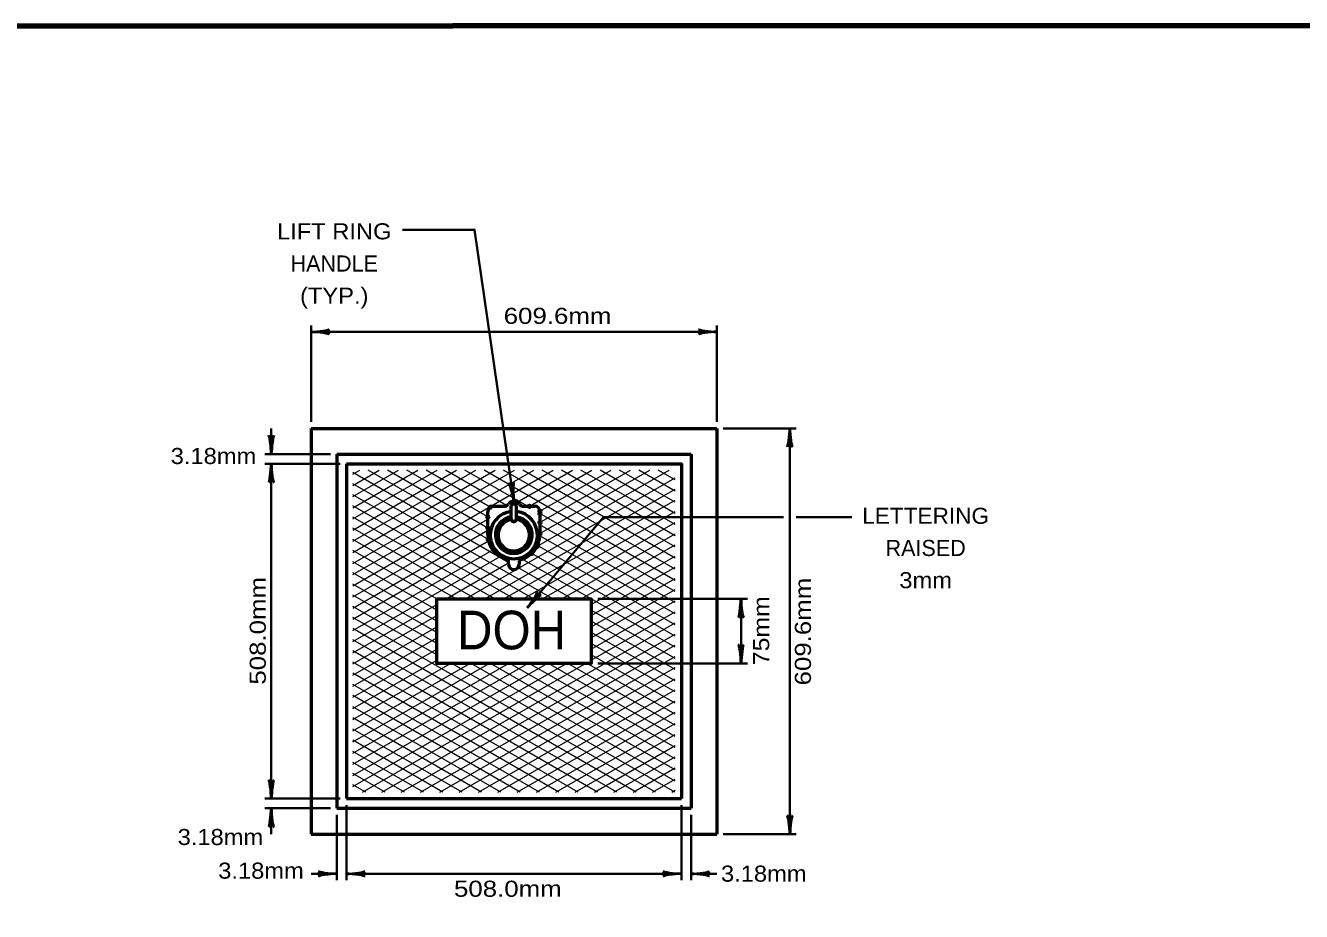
# Model space of a CAD drawing. Extents: x 918 to 1774, y -8 to 536.
# Drawn here: x 1291.6 to 1529.3, y 364.7 to 529.8 of the extents above; entities that cross this region are included whole.
import ezdxf
from ezdxf.enums import TextEntityAlignment as Align

# ---------------------------------------------------------------- set-up
doc = ezdxf.new("R2010")
doc.units = 0
doc.header["$LTSCALE"] = 1.2
doc.header["$PDMODE"] = 32
doc.header["$PDSIZE"] = 0.6
doc.layers.add('1', color=7, linetype='Continuous', lineweight=35)

msp = doc.modelspace()

# ---------------------------------------------------------------- linework, layer by layer
at = {"layer": '1'}
for p, q in [((1344.782, 455.942), (1344.782, 473.928)), ((1420.382, 455.942), (1420.382, 473.928)), ((1344.782, 472.728), (1420.382, 472.728)), ((1337.367, 454.743), (1337.367, 449.942)), ((1421.582, 454.743), (1435.184, 454.743)), ((1433.984, 454.743), (1433.984, 379.143)), ((1348.382, 449.942), (1336.167, 449.942)), ((1350.182, 448.143), (1336.167, 448.143)), ((1337.367, 448.143), (1337.367, 385.743)), ((1385.08, 421.334), (1399.25, 438.183)), ((1399.25, 438.183), (1432.784, 438.183)), ((1435.184, 438.183), (1445.504, 438.183)), ((1398.182, 422.942), (1426.081, 422.942)), ((1424.881, 422.942), (1424.881, 410.942)), ((1398.182, 410.942), (1426.081, 410.942)), ((1350.182, 385.743), (1336.167, 385.743)), ((1348.382, 383.942), (1336.167, 383.942)), ((1337.367, 383.942), (1337.367, 379.143)), ((1349.582, 382.743), (1349.582, 370.528)), ((1351.382, 384.543), (1351.382, 370.528)), ((1413.782, 384.543), (1413.782, 370.528)), ((1415.582, 382.743), (1415.582, 370.528)), ((1421.582, 379.143), (1435.184, 379.143)), ((1344.782, 371.728), (1349.582, 371.728)), ((1351.382, 371.728), (1413.782, 371.728)), ((1415.582, 371.728), (1420.382, 371.728))]:
    msp.add_line(p, q, dxfattribs=at)
at = {"layer": '1', "lineweight": 53}
for p, q in [((1344.782, 454.743), (1344.782, 379.143)), ((1344.782, 454.743), (1420.382, 454.743)), ((1420.382, 454.743), (1420.382, 379.143)), ((1349.582, 449.942), (1349.582, 383.942)), ((1349.582, 449.942), (1415.582, 449.942)), ((1415.582, 449.942), (1415.582, 383.942)), ((1351.382, 448.143), (1351.382, 385.743)), ((1378.683, 440.226), (1378.681, 440.218)), ((1378.681, 440.218), (1380.742, 440.218)), ((1378.681, 440.218), (1380.742, 440.218)), ((1382.083, 437.826), (1382.083, 440.218)), ((1383.055, 437.826), (1383.055, 440.218)), ((1384.396, 440.218), (1386.457, 440.218)), ((1384.396, 440.218), (1386.457, 440.218)), ((1377.709, 434.969), (1377.709, 439.245)), ((1377.709, 434.969), (1377.709, 439.245)), ((1387.429, 439.245), (1387.429, 435.008)), ((1387.429, 439.245), (1387.429, 435.008)), ((1381.578, 429.37), (1381.578, 430.012)), ((1381.578, 429.37), (1381.578, 430.012)), ((1383.541, 430.012), (1383.541, 429.37)), ((1383.541, 430.012), (1383.541, 429.37)), ((1351.382, 385.743), (1413.782, 385.743)), ((1349.582, 383.942), (1415.582, 383.942)), ((1344.782, 379.143), (1420.382, 379.143))]:
    msp.add_line(p, q, dxfattribs=at)
at = {"layer": '1', "lineweight": 13}
for p, q in [((1352.582, 446.186), (1353.893, 446.942)), ((1352.582, 444.107), (1357.493, 446.942)), ((1352.582, 442.029), (1361.093, 446.942)), ((1352.582, 439.95), (1364.693, 446.942)), ((1352.582, 437.872), (1368.293, 446.942)), ((1352.582, 435.793), (1371.893, 446.942)), ((1352.582, 433.715), (1375.493, 446.942)), ((1352.582, 431.637), (1379.093, 446.942)), ((1352.582, 429.558), (1382.693, 446.942)), ((1352.582, 427.48), (1386.293, 446.942)), ((1352.582, 425.401), (1389.893, 446.942)), ((1377.813, 434.022), (1355.435, 446.942)), ((1377.709, 436.161), (1359.035, 446.942)), ((1377.709, 438.24), (1362.635, 446.942)), ((1378.163, 440.056), (1366.235, 446.942)), ((1381.219, 440.37), (1369.835, 446.942)), ((1385.083, 440.218), (1373.435, 446.942)), ((1412.582, 426.419), (1377.035, 446.942)), ((1412.582, 428.498), (1380.635, 446.942)), ((1383.179, 440.988), (1393.493, 446.942)), ((1412.582, 430.576), (1384.235, 446.942)), ((1385.445, 440.218), (1397.093, 446.942)), ((1386.871, 432.727), (1411.493, 446.942)), ((1387.426, 439.283), (1400.693, 446.942)), ((1387.429, 437.206), (1404.293, 446.942)), ((1387.429, 435.128), (1407.893, 446.942)), ((1412.582, 432.655), (1387.835, 446.942)), ((1412.582, 434.733), (1391.435, 446.942)), ((1412.582, 436.812), (1395.035, 446.942)), ((1412.582, 438.89), (1398.635, 446.942)), ((1412.582, 440.969), (1402.235, 446.942)), ((1412.582, 443.047), (1405.835, 446.942)), ((1412.582, 445.126), (1409.435, 446.942)), ((1381.578, 429.771), (1352.582, 446.511)), ((1373.524, 422.942), (1412.582, 445.493)), ((1389.804, 422.942), (1352.582, 444.433)), ((1386.204, 422.942), (1352.582, 442.354)), ((1377.124, 422.942), (1412.582, 443.414)), ((1382.604, 422.942), (1352.582, 440.276)), ((1380.724, 422.942), (1412.582, 441.336)), ((1379.004, 422.942), (1352.582, 438.197)), ((1352.582, 423.323), (1377.709, 437.83)), ((1384.324, 422.942), (1412.582, 439.257)), ((1412.582, 424.341), (1387.429, 438.863)), ((1375.404, 422.942), (1352.582, 436.119)), ((1352.582, 421.244), (1377.709, 435.751)), ((1412.582, 422.262), (1387.429, 436.785)), ((1387.924, 422.942), (1412.582, 437.179)), ((1391.524, 422.942), (1412.582, 435.101)), ((1371.804, 422.942), (1352.582, 434.04)), ((1352.582, 419.166), (1377.868, 433.764)), ((1412.582, 418.106), (1386.95, 432.904)), ((1412.582, 420.184), (1387.405, 434.72)), ((1395.124, 422.942), (1412.582, 433.022)), ((1352.582, 417.087), (1378.627, 432.124)), ((1368.204, 422.942), (1352.582, 431.962)), ((1352.582, 415.009), (1380.008, 430.843)), ((1412.582, 413.949), (1384.133, 430.374)), ((1412.582, 416.027), (1385.893, 431.436)), ((1396.982, 421.937), (1412.582, 430.944)), ((1368.182, 420.877), (1352.582, 429.883)), ((1369.924, 422.942), (1381.578, 429.671)), ((1393.404, 422.942), (1383.29, 428.782)), ((1396.982, 419.858), (1412.582, 428.865)), ((1368.182, 418.798), (1352.582, 427.805)), ((1368.182, 416.72), (1352.582, 425.727)), ((1396.982, 417.78), (1412.582, 426.787)), ((1368.182, 414.641), (1352.582, 423.648)), ((1396.982, 415.702), (1412.582, 424.708)), ((1352.582, 412.93), (1368.182, 421.937)), ((1368.182, 412.563), (1352.582, 421.57)), ((1396.982, 413.623), (1412.582, 422.63)), ((1412.582, 411.87), (1396.982, 420.877)), ((1352.582, 410.852), (1368.182, 419.858)), ((1408.958, 386.942), (1352.582, 419.491)), ((1357.97, 386.942), (1412.582, 418.473)), ((1396.982, 411.545), (1412.582, 420.551)), ((1412.582, 409.792), (1396.982, 418.798)), ((1352.582, 408.773), (1368.182, 417.78)), ((1405.358, 386.942), (1352.582, 417.413)), ((1361.57, 386.942), (1412.582, 416.394)), ((1412.582, 407.713), (1396.982, 416.72)), ((1352.582, 406.695), (1368.182, 415.702)), ((1401.758, 386.942), (1352.582, 415.334)), ((1352.582, 404.617), (1368.182, 413.623)), ((1365.17, 386.942), (1412.582, 414.316)), ((1412.582, 405.635), (1396.982, 414.641)), ((1398.158, 386.942), (1352.582, 413.256)), ((1352.582, 402.538), (1368.182, 411.545)), ((1368.77, 386.942), (1412.582, 412.238)), ((1412.582, 403.556), (1396.982, 412.563)), ((1394.558, 386.942), (1352.582, 411.177)), ((1352.582, 400.46), (1370.739, 410.942)), ((1352.582, 398.381), (1374.339, 410.942)), ((1352.582, 396.303), (1377.939, 410.942)), ((1352.582, 394.224), (1381.539, 410.942)), ((1352.582, 392.146), (1385.139, 410.942)), ((1352.582, 390.067), (1388.739, 410.942)), ((1352.582, 387.989), (1392.339, 410.942)), ((1390.958, 386.942), (1352.582, 409.099)), ((1354.37, 386.942), (1395.939, 410.942)), ((1412.558, 386.942), (1370.989, 410.942)), ((1372.37, 386.942), (1412.582, 410.159)), ((1412.582, 389.007), (1374.589, 410.942)), ((1412.582, 391.086), (1378.189, 410.942)), ((1412.582, 393.164), (1381.789, 410.942)), ((1412.582, 395.242), (1385.389, 410.942)), ((1412.582, 397.321), (1388.989, 410.942)), ((1412.582, 399.399), (1392.589, 410.942)), ((1412.582, 401.478), (1396.189, 410.942)), ((1387.358, 386.942), (1352.582, 407.02)), ((1375.97, 386.942), (1412.582, 408.081)), ((1383.758, 386.942), (1352.582, 404.942)), ((1379.57, 386.942), (1412.582, 406.002)), ((1380.158, 386.942), (1352.582, 402.863)), ((1383.17, 386.942), (1412.582, 403.924)), ((1386.77, 386.942), (1412.582, 401.845)), ((1376.558, 386.942), (1352.582, 400.785)), ((1390.37, 386.942), (1412.582, 399.767)), ((1372.958, 386.942), (1352.582, 398.707)), ((1393.97, 386.942), (1412.582, 397.688)), ((1369.358, 386.942), (1352.582, 396.628)), ((1397.57, 386.942), (1412.582, 395.61)), ((1365.758, 386.942), (1352.582, 394.55)), ((1362.158, 386.942), (1352.582, 392.471)), ((1401.17, 386.942), (1412.582, 393.531)), ((1358.558, 386.942), (1352.582, 390.393)), ((1404.77, 386.942), (1412.582, 391.453)), ((1354.958, 386.942), (1352.582, 388.314)), ((1408.37, 386.942), (1412.582, 389.374)), ((1411.97, 386.942), (1412.582, 387.296))]:
    msp.add_line(p, q, dxfattribs=at)
at = {"layer": '1', "lineweight": 158}
msp.add_lwpolyline([(1766.999, 529.818), (975.299, 529.718), (975.399, 3.718)], dxfattribs=at)
at = {"layer": '1'}
msp.add_lwpolyline([(1382.565, 441.164), (1375.253, 491.764), (1361.847, 491.764)], dxfattribs=at)
at = {"layer": '1', "lineweight": 53}
msp.add_lwpolyline([(1351.382, 448.143), (1413.782, 448.143), (1413.782, 385.743)], dxfattribs=at)
msp.add_lwpolyline([(1368.182, 422.942), (1396.982, 422.942), (1396.982, 410.942), (1368.182, 410.942)], close=True, dxfattribs=at)
for centre, radius, start, end in [((1378.683, 439.246), 0.98, 90, 180), ((1378.683, 439.246), 0.98, 90, 180), ((1380.739, 441.205), 0.98, 270, 324.40119), ((1380.739, 441.205), 0.98, 270, 324.40119), ((1382.565, 439.898), 1.266, 35.59881, 144.40119), ((1382.565, 439.898), 1.266, 35.59881, 144.40119), ((1382.565, 440.184), 0.49, 4.83802, 175.16198), ((1384.391, 441.205), 0.98, 215.59881, 270), ((1384.391, 441.205), 0.98, 215.59881, 270), ((1386.448, 439.246), 0.98, 0, 90), ((1386.448, 439.246), 0.98, 0, 90), ((1382.555, 434.859), 4.409, 96.21818, 83.50424), ((1382.555, 434.859), 3.429, 98.00514, 81.63652), ((1382.555, 434.859), 2.939, 99.14766, 80.4482), ((1382.565, 437.869), 0.49, 184.83802, 355.16198), ((1382.565, 434.966), 4.862, 283.87448, 0.55336), ((1382.565, 434.966), 4.862, 283.87448, 0.55336), ((1382.565, 434.966), 4.862, 180, 256.12552), ((1382.565, 434.966), 4.862, 180, 256.12552), ((1381.341, 430.007), 0.245, 0, 76.12552), ((1381.341, 430.007), 0.245, 0, 76.12552), ((1382.565, 429.424), 0.981, 183.23003, 356.76998), ((1382.565, 429.424), 0.981, 183.23003, 356.76998), ((1383.79, 430.007), 0.245, 103.87448, 180), ((1383.79, 430.007), 0.245, 103.87448, 180)]:
    msp.add_arc(centre, radius, start, end, dxfattribs=at)
at = {"layer": '1', "lineweight": 40}
for centre, major_axis, ratio, start_param, end_param in [((1346.092, 473.059), (-2.143, -0.187), 0.122415, 0.8963533, 3.1415927), ((1346.092, 473.059), (-2.143, -0.187), 0.122415, 0.8963533, 3.1415927), ((1419.038, 472.982), (2.108, -0.211), 0.07063, 3.1407148, 5.41811), ((1346.127, 472.474), (-2.108, 0.211), 0.07063, 3.1407148, 5.41811), ((1346.127, 472.474), (-2.108, 0.211), 0.07063, 3.1407148, 5.41811), ((1419.073, 472.396), (2.143, 0.187), 0.122415, 0.8963533, 3.1415927), ((1433.73, 453.398), (0.211, 2.108), 0.07063, 3.1407148, 5.41811), ((1433.73, 453.398), (0.211, 2.108), 0.07063, 3.1407148, 5.41811), ((1434.315, 453.433), (-0.187, 2.143), 0.122415, 0.8963533, 3.1415927), ((1434.315, 453.433), (-0.187, 2.143), 0.122415, 0.8963533, 3.1415927), ((1337.036, 451.252), (0.187, -2.143), 0.122415, 0.8963533, 3.1415927), ((1337.621, 451.287), (-0.211, -2.108), 0.07063, 3.1407148, 5.41811), ((1337.113, 446.798), (0.211, 2.108), 0.07063, 3.1407148, 5.41811), ((1337.113, 446.798), (0.211, 2.108), 0.07063, 3.1407148, 5.41811), ((1337.699, 446.833), (-0.187, 2.143), 0.122415, 0.8963533, 3.1415927), ((1337.699, 446.833), (-0.187, 2.143), 0.122415, 0.8963533, 3.1415927), ((1382.05, 442.413), (0.492, -2.094), 0.122415, 0.8963533, 3.1415927), ((1382.624, 442.531), (0.093, -2.116), 0.07063, 3.1407148, 5.41811), ((1385.669, 422.549), (-1.236, -1.761), 0.122415, 0.8963533, 3.1415927), ((1386.139, 422.199), (-1.518, -1.477), 0.07063, 3.1407148, 5.41811), ((1424.627, 421.598), (0.211, 2.108), 0.07063, 3.1407148, 5.41811), ((1424.627, 421.598), (0.211, 2.108), 0.07063, 3.1407148, 5.41811), ((1425.213, 421.633), (-0.187, 2.143), 0.122415, 0.8963533, 3.1415927), ((1425.213, 421.633), (-0.187, 2.143), 0.122415, 0.8963533, 3.1415927), ((1424.55, 412.252), (0.187, -2.143), 0.122415, 0.8963533, 3.1415927), ((1425.135, 412.287), (-0.211, -2.108), 0.07063, 3.1407148, 5.41811), ((1337.036, 387.052), (0.187, -2.143), 0.122415, 0.8963533, 3.1415927), ((1337.036, 387.052), (0.187, -2.143), 0.122415, 0.8963533, 3.1415927), ((1337.621, 387.087), (-0.211, -2.108), 0.07063, 3.1407148, 5.41811), ((1337.621, 387.087), (-0.211, -2.108), 0.07063, 3.1407148, 5.41811), ((1337.113, 382.598), (0.211, 2.108), 0.07063, 3.1407148, 5.41811), ((1337.699, 382.633), (-0.187, 2.143), 0.122415, 0.8963533, 3.1415927), ((1433.652, 380.452), (0.187, -2.143), 0.122415, 0.8963533, 3.1415927), ((1434.238, 380.487), (-0.211, -2.108), 0.07063, 3.1407148, 5.41811), ((1348.273, 371.396), (2.143, 0.187), 0.122415, 0.8963533, 3.1415927), ((1348.238, 371.982), (2.108, -0.211), 0.07063, 3.1407148, 5.41811), ((1352.727, 371.474), (-2.108, 0.211), 0.07063, 3.1407148, 5.41811), ((1352.727, 371.474), (-2.108, 0.211), 0.07063, 3.1407148, 5.41811), ((1352.692, 372.059), (-2.143, -0.187), 0.122415, 0.8963533, 3.1415927), ((1352.692, 372.059), (-2.143, -0.187), 0.122415, 0.8963533, 3.1415927), ((1412.473, 371.396), (2.143, 0.187), 0.122415, 0.8963533, 3.1415927), ((1412.473, 371.396), (2.143, 0.187), 0.122415, 0.8963533, 3.1415927), ((1412.438, 371.982), (2.108, -0.211), 0.07063, 3.1407148, 5.41811), ((1412.438, 371.982), (2.108, -0.211), 0.07063, 3.1407148, 5.41811), ((1416.927, 371.474), (-2.108, 0.211), 0.07063, 3.1407148, 5.41811), ((1416.892, 372.059), (-2.143, -0.187), 0.122415, 0.8963533, 3.1415927)]:
    msp.add_ellipse(centre, major_axis=major_axis, ratio=ratio, start_param=start_param, end_param=end_param, dxfattribs=at)
at = {"layer": '1'}
for p in [(1378.163, 440.056), (1383.179, 440.988), (1385.445, 440.218), (1377.709, 438.24), (1387.426, 439.283), (1387.429, 438.863), (1387.429, 437.206), (1377.709, 436.161), (1387.429, 435.128), (1377.813, 434.022), (1386.871, 432.727), (1386.95, 432.904), (1385.893, 431.436)]:
    msp.add_point(p, dxfattribs=at)

# ---------------------------------------------------------------- texts
for s, width, p in [('LIFT RING', 1.1, (1349.104, 489.965)), ('(TYP.)', 1.1, (1349.104, 477.965)), ('LETTERING', 1.05, (1459.279, 436.951)), ('3mm', 1.1, (1459.279, 424.951))]:
    msp.add_text(s, height=3, dxfattribs=dict(at, width=width)).set_placement(p, align=Align.CENTER)
for s, p in [('HANDLE', (1349.104, 483.965)), ('RAISED', (1459.279, 430.951))]:
    msp.add_text(s, height=3, dxfattribs=at).set_placement(p, align=Align.CENTER)
for s, height, width, p in [('609.6mm', 3, 1.2, (1380.672, 474.209)), ('3.18mm', 3, 1.1, (1318.635, 448.089)), ('DOH', 7.2, 0.95, (1371.975, 413.561)), ('3.18mm', 3, 1.1, (1319.926, 377.087)), ('3.18mm', 3, 1.1, (1327.485, 370.816)), ('3.18mm', 3, 1.1, (1421.149, 370.263)), ('508.0mm', 3, 1.2, (1371.407, 367.443))]:
    msp.add_text(s, height=height, dxfattribs=dict(at, width=width)).set_placement(p)
for s, width, p in [('508.0mm', 1.2, (1336.35, 406.978)), ('609.6mm', 1.2, (1437.913, 406.834)), ('75mm', 1.15, (1430.136, 410.622))]:
    msp.add_text(s, height=3, rotation=90, dxfattribs=dict(at, width=width)).set_placement(p)

doc.saveas('drawing.dxf')
